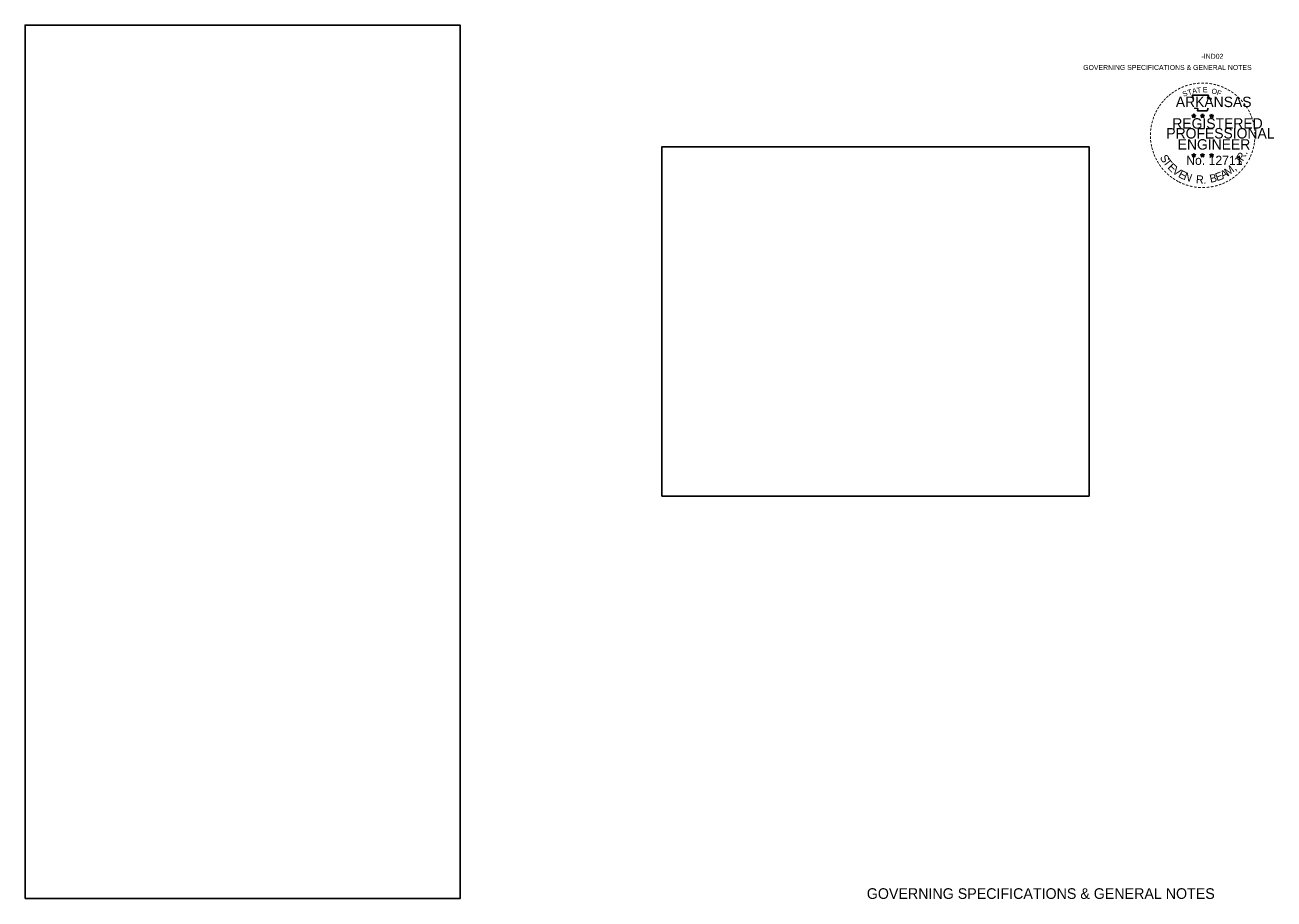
# Model space of a CAD drawing. Extents: x 1224738 to 1228169, y 151313 to 152339.
# Drawn here: x 1226703 to 1228169, y 151313 to 152339 of the extents above; entities that cross this region are included whole.
import ezdxf

# ---------------------------------------------------------------- set-up
doc = ezdxf.new("R2010")
doc.units = 0
doc.layers.add('R_Axis Annot', color=7, linetype='Continuous')
doc.layers.add('R_Border', color=7, linetype='Continuous')

msp = doc.modelspace()

# ---------------------------------------------------------------- linework, layer by layer
at = {"layer": 'R_Axis Annot'}
for p, q in [((1228073.1, 152233.1), (1228075.2, 152232.4)), ((1228073.1, 152233.1), (1228074.6, 152232.8)), ((1228073.1, 152233.1), (1228074.5, 152232.4)), ((1228073.9, 152230.6), (1228075.2, 152232.4)), ((1228073.9, 152230.6), (1228074.7, 152232.1)), ((1228073.9, 152230.6), (1228075.2, 152231.9)), ((1228075.2, 152234.7), (1228075, 152233.1)), ((1228075.2, 152232.4), (1228075.2, 152234.7)), ((1228075.2, 152234.7), (1228075.5, 152233.1)), ((1228077.3, 152233.1), (1228075.2, 152232.4)), ((1228076.5, 152230.6), (1228075.2, 152232.4)), ((1228076.5, 152230.6), (1228075.2, 152231.9)), ((1228077.3, 152233.1), (1228075.6, 152232.8)), ((1228076.5, 152230.6), (1228075.7, 152232.4)), ((1228077.3, 152233.1), (1228076.1, 152232.5)), ((1228083.3, 152233.1), (1228085.4, 152232.4)), ((1228083.3, 152233.1), (1228084.8, 152232.8)), ((1228083.3, 152233.1), (1228084.7, 152232.4)), ((1228084.1, 152230.6), (1228085.4, 152232.4)), ((1228084.1, 152230.6), (1228084.9, 152232.1)), ((1228084.1, 152230.6), (1228085.4, 152231.9)), ((1228085.4, 152234.7), (1228085.2, 152233.1)), ((1228085.4, 152232.4), (1228085.4, 152234.7)), ((1228085.4, 152234.7), (1228085.7, 152233.1)), ((1228087.5, 152233.1), (1228085.4, 152232.4)), ((1228086.7, 152230.6), (1228085.4, 152232.4)), ((1228086.7, 152230.6), (1228085.4, 152231.9)), ((1228087.5, 152233.1), (1228085.8, 152232.8)), ((1228086.7, 152230.6), (1228085.9, 152232.4)), ((1228087.5, 152233.1), (1228086.3, 152232.5)), ((1228094, 152233), (1228096.2, 152232.4)), ((1228094, 152233), (1228095.6, 152232.8)), ((1228094, 152233), (1228095.5, 152232.3)), ((1228094.9, 152230.5), (1228096.2, 152232.4)), ((1228094.9, 152230.5), (1228095.6, 152232)), ((1228094.9, 152230.5), (1228096.2, 152231.9)), ((1228096.2, 152234.6), (1228095.9, 152233.1)), ((1228096.2, 152232.4), (1228096.2, 152234.6)), ((1228096.2, 152234.6), (1228096.5, 152233.1)), ((1228098.3, 152233), (1228096.2, 152232.4)), ((1228097.5, 152230.5), (1228096.2, 152232.4)), ((1228097.5, 152230.5), (1228096.2, 152231.9)), ((1228098.3, 152233), (1228096.5, 152232.7)), ((1228097.5, 152230.5), (1228096.6, 152232.3)), ((1228098.3, 152233), (1228097, 152232.4)), ((1228075.2, 152188.4), (1228074.9, 152186.9)), ((1228075.2, 152186.2), (1228075.2, 152188.4)), ((1228075.2, 152188.4), (1228075.5, 152186.9)), ((1228085.4, 152188.4), (1228085.1, 152186.9)), ((1228085.4, 152186.2), (1228085.4, 152188.4)), ((1228085.4, 152188.4), (1228085.7, 152186.9)), ((1228096.2, 152188.4), (1228095.9, 152186.8)), ((1228096.2, 152186.1), (1228096.2, 152188.4)), ((1228096.2, 152188.4), (1228096.5, 152186.8)), ((1228073.1, 152186.9), (1228075.2, 152186.2)), ((1228073.1, 152186.9), (1228074.6, 152186.6)), ((1228073.1, 152186.9), (1228074.5, 152186.1)), ((1228073.9, 152184.4), (1228075.2, 152186.2)), ((1228073.9, 152184.4), (1228074.6, 152185.9)), ((1228073.9, 152184.4), (1228075.2, 152185.7)), ((1228077.3, 152186.9), (1228075.2, 152186.2)), ((1228076.5, 152184.4), (1228075.2, 152186.2)), ((1228076.5, 152184.4), (1228075.2, 152185.7)), ((1228077.3, 152186.9), (1228075.6, 152186.6)), ((1228076.5, 152184.4), (1228075.7, 152186.2)), ((1228077.3, 152186.9), (1228076.1, 152186.3)), ((1228083.2, 152186.9), (1228085.4, 152186.2)), ((1228083.2, 152186.9), (1228084.8, 152186.6)), ((1228083.2, 152186.9), (1228084.7, 152186.1)), ((1228084.1, 152184.4), (1228085.4, 152186.2)), ((1228084.1, 152184.4), (1228084.8, 152185.9)), ((1228084.1, 152184.4), (1228085.4, 152185.7)), ((1228087.5, 152186.9), (1228085.4, 152186.2)), ((1228086.7, 152184.4), (1228085.4, 152186.2)), ((1228086.7, 152184.4), (1228085.4, 152185.7)), ((1228087.5, 152186.9), (1228085.7, 152186.6)), ((1228086.7, 152184.4), (1228085.8, 152186.2)), ((1228087.5, 152186.9), (1228086.2, 152186.3)), ((1228094, 152186.8), (1228096.2, 152186.1)), ((1228094, 152186.8), (1228095.6, 152186.5)), ((1228094, 152186.8), (1228095.5, 152186.1)), ((1228094.8, 152184.3), (1228096.2, 152186.1)), ((1228094.8, 152184.3), (1228095.6, 152185.8)), ((1228094.8, 152184.3), (1228096.1, 152185.7)), ((1228097.5, 152184.3), (1228096.1, 152185.6)), ((1228098.3, 152186.8), (1228096.2, 152186.1)), ((1228097.5, 152184.3), (1228096.2, 152186.1)), ((1228098.3, 152186.8), (1228096.5, 152186.5)), ((1228097.5, 152184.3), (1228096.6, 152186.1)), ((1228098.3, 152186.8), (1228097, 152186.2))]:
    msp.add_line(p, q, dxfattribs=at)
for points in [[(1228073.3, 152256.8), (1228075, 152251.7)], [(1228094.8, 152251.2), (1228095.6, 152252.9), (1228091.4, 152252.7), (1228092.4, 152256.8), (1228073.3, 152256.8)], [(1228075.2, 152234.7), (1228076.5, 152230.6), (1228073.1, 152233.1), (1228077.3, 152233.1), (1228073.9, 152230.6), (1228075.2, 152234.7)], [(1228076.3, 152242), (1228076.3, 152241.5), (1228079.8, 152241.3), (1228079.4, 152238.5), (1228090.9, 152238.5), (1228092.1, 152241.7)], [(1228085.4, 152234.7), (1228086.7, 152230.6), (1228083.3, 152233.1), (1228087.5, 152233.1), (1228084.1, 152230.6), (1228085.4, 152234.7)], [(1228096.2, 152234.6), (1228097.5, 152230.5), (1228094, 152233), (1228098.3, 152233), (1228094.9, 152230.5), (1228096.2, 152234.6)], [(1228075.2, 152188.4), (1228076.5, 152184.4), (1228073.1, 152186.9), (1228077.3, 152186.9), (1228073.9, 152184.4), (1228075.2, 152188.4)], [(1228085.4, 152188.4), (1228086.7, 152184.4), (1228083.2, 152186.9), (1228087.5, 152186.9), (1228084.1, 152184.4), (1228085.4, 152188.4)], [(1228096.2, 152188.4), (1228097.5, 152184.3), (1228094, 152186.8), (1228098.3, 152186.8), (1228094.8, 152184.3), (1228096.2, 152188.4)]]:
    msp.add_lwpolyline(points, dxfattribs=at)
for centre, radius in [((1228075.2, 152232.4), 1.05), ((1228075.2, 152232.4), 0.882), ((1228075.2, 152232.4), 0.707), ((1228075.2, 152232.4), 0.605), ((1228075.2, 152232.4), 0.456), ((1228075.2, 152232.4), 0.302), ((1228075.2, 152232.4), 0.181), ((1228085.4, 152232.4), 1.05), ((1228085.4, 152232.4), 0.882), ((1228085.4, 152232.4), 0.707), ((1228085.4, 152232.4), 0.605), ((1228085.4, 152232.4), 0.456), ((1228085.4, 152232.4), 0.302), ((1228085.4, 152232.4), 0.181), ((1228096.2, 152232.4), 1.05), ((1228096.2, 152232.4), 0.882), ((1228096.2, 152232.4), 0.707), ((1228096.2, 152232.4), 0.605), ((1228096.2, 152232.4), 0.456), ((1228096.2, 152232.4), 0.302), ((1228096.2, 152232.4), 0.181), ((1228075.2, 152186.2), 1.05), ((1228075.2, 152186.2), 0.882), ((1228085.4, 152186.2), 1.05), ((1228085.4, 152186.2), 0.882), ((1228096.2, 152186.1), 1.05), ((1228075.2, 152186.2), 0.707), ((1228075.2, 152186.2), 0.605), ((1228075.2, 152186.2), 0.456), ((1228075.2, 152186.2), 0.302), ((1228075.2, 152186.2), 0.181), ((1228085.4, 152186.2), 0.707), ((1228085.4, 152186.2), 0.605), ((1228085.4, 152186.2), 0.456), ((1228085.4, 152186.2), 0.302), ((1228085.4, 152186.2), 0.181), ((1228096.2, 152186.1), 0.882), ((1228096.2, 152186.1), 0.707), ((1228096.2, 152186.1), 0.605), ((1228096.2, 152186.1), 0.456), ((1228096.2, 152186.1), 0.302), ((1228096.2, 152186.1), 0.181)]:
    msp.add_circle(centre, radius, dxfattribs=at)
at = {"layer": 'R_Border'}
for points in [[(1226702.6, 151313.1), (1227213.5, 151313.1), (1227213.5, 152339.2), (1226702.6, 152339.2)], [(1227450.6, 151785.9), (1227952.2, 151785.9), (1227952.2, 152196.3), (1227450.6, 152196.3)]]:
    msp.add_lwpolyline(points, close=True, dxfattribs=at)

# ---------------------------------------------------------------- texts
at = {"layer": 'R_Axis Annot'}
for s, height, p in [('-IND02', 5.86, (1228084.3, 152299.5)), ('GOVERNING SPECIFICATIONS & GENERAL NOTES ', 5.862, (1227945.3, 152286.4)), ('ARKANSAS', 12.21, (1228054.1, 152242.8)), ('PROFESSIONAL', 12.208, (1228043, 152205.9)), ('REGISTERED', 12.21, (1228050, 152217.5)), ('ENGINEER', 12.21, (1228056.3, 152192.9)), ('No. 12711', 10.72, (1228066.3, 152174.9))]:
    msp.add_text(s, height=height, dxfattribs=at).set_placement(p)
for s, height, rotation, p in [('-', 9.77, 36.2317, (1228050.8, 152255.4)), ('-', 9.77, 34.0636, (1228054.3, 152257.8)), ('-', 9.77, 28.7918, (1228058, 152260.1)), ('-', 9.77, 24.3072, (1228061.8, 152262)), ('S', 6.1, 21.594, (1228063.3, 152254.8)), ('-', 9.77, 19.1761, (1228065.7, 152263.7)), ('T', 6.1, 16.4036, (1228068.9, 152256.8)), ('-', 9.77, 13.6302, (1228070.3, 152265.1)), ('A', 6.1, 11.2132, (1228073.9, 152258.4)), ('-', 9.77, 10.2193, (1228074.4, 152266.1)), ('T', 6.1, 6.0228, (1228079.1, 152259.4)), ('-', 9.77, 5.8968, (1228078.9, 152266.8)), ('-', 9.77, 0.1862, (1228083.6, 152267.2)), ('E', 6.1, 0.8323, (1228085.8, 152260.1)), ('-', 9.77, 357.743, (1228088, 152267.2)), ('-', 9.77, 352.1617, (1228092.5, 152266.8)), ('O', 6.1, 350.4515, (1228095.6, 152258.8)), ('-', 9.77, 347.2049, (1228096.9, 152266.1)), ('F', 6.1, 340.0707, (1228101.5, 152257.4)), ('-', 9.77, 342.3362, (1228100.8, 152265.2)), ('-', 9.77, 337.8551, (1228105.3, 152263.8)), ('-', 9.77, 334.1211, (1228109.1, 152262.2)), ('-', 9.77, 329.6409, (1228112.7, 152260.4)), ('-', 9.77, 325.8627, (1228116.6, 152258.2)), ('-', 9.77, 54.2325, (1228037.5, 152241.2)), ('-', 9.77, 50.6142, (1228040, 152244.7)), ('-', 9.77, 48.4231, (1228042.5, 152247.6)), ('-', 9.77, 42.9622, (1228045.2, 152250.6)), ('-', 9.77, 38.9507, (1228047.9, 152253.1)), ('-', 9.77, 320.5297, (1228120.3, 152255.6)), ('-', 9.77, 315.5786, (1228124, 152252.6)), ('-', 9.77, 309.8797, (1228127.4, 152249.3)), ('-', 9.77, 306.6522, (1228130.6, 152245.6)), ('-', 9.77, 72.3945, (1228030.7, 152226.7)), ('-', 9.77, 67.7743, (1228032, 152230.5)), ('-', 9.77, 62.8713, (1228033.6, 152234.3)), ('-', 9.77, 58.0706, (1228035.5, 152238)), ('-', 8.55, 303.6753, (1228133.6, 152242.1)), ('-', 9.77, 299.6684, (1228135.6, 152238.4)), ('-', 9.77, 294.6628, (1228137.5, 152234.7)), ('-', 9.77, 290.5728, (1228139.1, 152231.2)), ('-', 9.77, 85.1863, (1228028.2, 152213.7)), ('-', 9.77, 81.2013, (1228028.7, 152218)), ('-', 9.77, 75.461, (1228029.5, 152222.3)), ('-', 9.77, 285.1233, (1228140.5, 152227.6)), ('-', 9.77, 280.5493, (1228141.8, 152223.1)), ('-', 9.77, 276.5962, (1228142.7, 152218.4)), ('-', 9.77, 94.1959, (1228028.3, 152205)), ('-', 9.77, 89.0622, (1228028.1, 152209.5)), ('-', 9.77, 98.9479, (1228028.7, 152201)), ('-', 9.77, 263.5172, (1228143.2, 152206.1)), ('-', 9.77, 274.3301, (1228143.1, 152214)), ('-', 9.77, 269.9407, (1228143.3, 152210.2)), ('-', 9.77, 101.7149, (1228029.6, 152196.5)), ('-', 9.77, 105.4578, (1228030.5, 152192.9)), ('-', 9.77, 109.0874, (1228031.9, 152189)), ('-', 9.77, 114.0643, (1228033.4, 152185.4)), ('R.', 9.4, 60.8264, (1228132.9, 152178.6)), ('-', 9.77, 247.8887, (1228139.6, 152189.5)), ('-', 9.77, 252.8681, (1228141, 152193.6)), ('-', 9.77, 255.7626, (1228142.1, 152198)), ('-', 9.77, 260.9953, (1228142.8, 152202.1)), ('-', 9.77, 115.7289, (1228035.3, 152181.6)), ('-', 9.77, 120.4471, (1228037.5, 152178)), ('-', 9.77, 125.8934, (1228039.9, 152174.6)), ('S', 9.4, 299.1736, (1228035.1, 152183.7)), ('T', 9.4, 307.2838, (1228038.6, 152177.7)), ('E', 9.4, 315.394, (1228043.8, 152171.2)), ('V', 9.4, 323.5042, (1228049.2, 152166.1)), ('M,', 9.4, 36.4958, (1228115.3, 152161.4)), ('J', 9.4, 52.7162, (1228129.3, 152173.9)), ('-', 9.77, 233.8452, (1228133.2, 152177)), ('-', 9.77, 239.0712, (1228135.6, 152181)), ('-', 9.77, 244.6197, (1228138, 152185.6)), ('-', 9.77, 130.7181, (1228042.7, 152171.2)), ('-', 9.77, 134.2238, (1228045.9, 152167.9)), ('-', 9.77, 138.9338, (1228049.1, 152165.1)), ('-', 9.77, 144.6463, (1228052.5, 152162.6)), ('-', 9.77, 148.0898, (1228055.9, 152160.3)), ('E', 9.4, 331.6144, (1228056.2, 152161.1)), ('N', 9.4, 339.7245, (1228062.6, 152157.8)), ('R.', 9.4, 355.9449, (1228077.5, 152153.5)), ('B', 9.4, 12.1653, (1228094.9, 152153.8)), ('E', 9.4, 20.2755, (1228102.5, 152155.6)), ('A', 9.4, 28.3856, (1228109.3, 152158.2)), ('-', 9.77, 212.2491, (1228117.8, 152161.8)), ('-', 9.77, 215.7363, (1228121.1, 152164.2)), ('-', 9.77, 221.0851, (1228124.4, 152167)), ('-', 9.77, 225.7653, (1228127.6, 152170.1)), ('-', 9.77, 231.2538, (1228130.5, 152173.6)), ('-', 9.77, 151.5704, (1228059.4, 152158.3)), ('-', 9.77, 154.6002, (1228062.6, 152156.8)), ('-', 9.77, 158.5612, (1228066.4, 152155.3)), ('-', 9.77, 162.7983, (1228070.6, 152154)), ('-', 9.77, 167.5555, (1228075, 152153)), ('-', 9.77, 173.1155, (1228079.7, 152152.3)), ('-', 9.77, 176.5183, (1228084.3, 152152)), ('-', 9.77, 181.5918, (1228088.8, 152152.1)), ('-', 9.77, 185.8167, (1228093.8, 152152.6)), ('-', 9.77, 191.2858, (1228098.2, 152153.4)), ('-', 9.77, 195.4743, (1228102.7, 152154.6)), ('-', 9.77, 200.7184, (1228106.8, 152156.1)), ('-', 9.77, 204.2516, (1228110.6, 152157.7)), ('-', 9.77, 207.3568, (1228114.4, 152159.7))]:
    msp.add_text(s, height=height, rotation=rotation, dxfattribs=at).set_placement(p)
at = {"layer": 'R_Border'}
msp.add_text('GOVERNING SPECIFICATIONS & GENERAL NOTES ', height=12.5, dxfattribs=at).set_placement((1227691.2, 151312.8))

doc.saveas('drawing.dxf')
